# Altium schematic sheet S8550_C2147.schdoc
size 127 x 101 mm
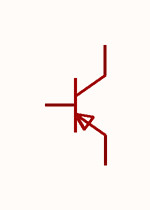
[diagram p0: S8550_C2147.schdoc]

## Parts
Q?  s8550 2ty(range:200-350)  [SOT-23-3_L2.9-W1.3-P1.90-LS2.4-BR]  (value not drawn)

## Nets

Not connected (* = marked no-connect by the designer): Q? 1(B) 2(E) 3(C)

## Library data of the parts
Q? = s8550 2ty(range:200-350): 晶体管类型:PNP;集电极电流(Ic):500mA;集射极击穿电压(Vceo):25V;耗散功率(Pd):300mW;直流电流增益(hFE):120;; Manufacturer: CJ(江苏长电/长晶); Symbol: S8550_C2147; AddInBom: yes; ModelId: c62791f0466c4ae2a892c056b845b0ca; ModelName: SOT-23-3P_L2.9-W1.3-H1.0-LS2.4-P0.95; ModelTransform: 98.425,114.173,0,180,0,0,0.0005,-0.0005,0; type: PNP; Current - Collector(Ic): 500mA; Collector - Emitter Voltage VCEO: 25V; Pd - Power Dissipation: 300mW; DC Current Gain: 120; Transition frequency(fT): 150MHz; Current - Collector Cutoff: 100nA; Vce Saturation(VCE(sat)): 600mV; Emitter-Base Voltage(Vebo): 5V; Number: 1个PNP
